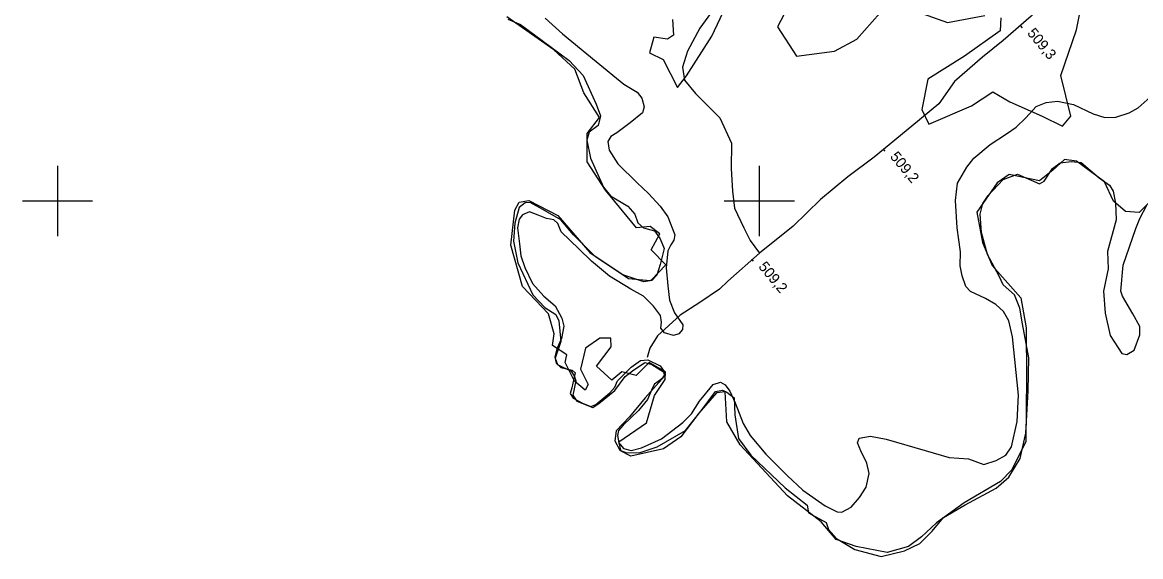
# Model space of a CAD drawing. Extents: x 347312 to 350503, y 6073086 to 6076432.
# Drawn here: x 348090 to 348408.7, y 6075298.7 to 6075450.8 of the extents above; entities that cross this region are included whole.
import ezdxf

# ---------------------------------------------------------------- set-up
doc = ezdxf.new("R2010")
doc.units = 0
for name, color, linetype in [('Level 2', 7, 'Continuous'), ('Level 22', 7, 'Continuous'), ('Level 3', 7, 'Continuous'), ('Level 4', 7, 'Continuous'), ('Level 44', 7, 'Continuous'), ('Level 61', 7, 'Continuous')]:
    doc.layers.add(name, color=color, linetype=linetype)

msp = doc.modelspace()

# ---------------------------------------------------------------- linework, layer by layer
at = {"layer": 'Level 2'}
for points in [[(348238.98, 6075452.05), (348243.95, 6075447.56), (348253.49, 6075439.72), (348261.38, 6075433.28), (348265.21, 6075430.93), (348266.57, 6075429.25), (348267.16, 6075426.82), (348266.74, 6075425.13), (348263.19, 6075422.28), (348259.41, 6075419.39), (348257.67, 6075418.32), (348256.83, 6075416.96), (348257.21, 6075414.47), (348259.71, 6075410.58), (348265.19, 6075405.18), (348268.47, 6075402.08), (348271.78, 6075398.47), (348273.92, 6075395.47), (348275.89, 6075390.32), (348275.69, 6075388.83), (348274.79, 6075387.54), (348273.93, 6075385.75), (348273.46, 6075380.96), (348273.98, 6075375.8), (348274.37, 6075371.74), (348275.81, 6075368.15), (348278.2, 6075364.69), (348278.1, 6075363.4), (348277.06, 6075362.13), (348275.58, 6075361.69), (348272.97, 6075362.43), (348271.99, 6075363.74), (348272.13, 6075365.45), (348271.85, 6075367.35), (348269.83, 6075370.06), (348266.96, 6075372.84), (348263.37, 6075374.89), (348257.32, 6075378.6), (348252.18, 6075382.81), (348248.56, 6075386.31), (348243.54, 6075391.16), (348242.58, 6075393.55), (348241.44, 6075394.59), (348239.38, 6075394.99), (348237, 6075395.92), (348234.47, 6075396.87), (348232.53, 6075396.04), (348231.56, 6075394.83), (348231.14, 6075392.35), (348231.71, 6075387.76), (348232.08, 6075384.34), (348233.18, 6075381), (348235.41, 6075376.47), (348238.58, 6075372.87), (348241.83, 6075370.13), (348243.77, 6075366.57), (348244.32, 6075364.36), (348243.59, 6075360.82), (348242.27, 6075357.84)], [(348363.99, 6075324.95), (348367.47, 6075326.08), (348370.25, 6075327.58), (348371.86, 6075329.98), (348373.48, 6075337.22), (348373.87, 6075344.64), (348372.11, 6075361.27), (348371.14, 6075365.83), (348369.55, 6075368.54), (348367.39, 6075370.5), (348364.47, 6075372.24), (348360.18, 6075374.19), (348358.85, 6075375.63), (348357.81, 6075378.66), (348357.27, 6075381.56), (348357.34, 6075385.5), (348356.36, 6075392.33), (348355.9, 6075400.13), (348356.5, 6075405.05), (348359.12, 6075409.63), (348361.12, 6075412.22), (348365.8, 6075416.09), (348370.48, 6075419.15), (348373.22, 6075421.01), (348375.96, 6075423.67), (348378.89, 6075426.9), (348381.71, 6075428.02), (348384.97, 6075428.44), (348389.5, 6075427.49), (348395.18, 6075424.83), (348398.46, 6075423.78), (348401.61, 6075423.84), (348405.39, 6075425.09), (348407.93, 6075426.53), (348411.43, 6075429.55)], [(348242.27, 6075357.84), (348241.72, 6075355.51), (348242.15, 6075353.75), (348243.43, 6075352.55), (348246.69, 6075351.82), (348247.49, 6075351.03), (348247.14, 6075349.4), (348246.57, 6075346.79), (348246.08, 6075345.18), (348246.97, 6075343.8), (348249.81, 6075342.32), (348251.98, 6075341.47), (348253.4, 6075342), (348257.43, 6075345.38), (348258.86, 6075346.98), (348259.59, 6075348.79), (348263.51, 6075352.62), (348266.12, 6075354.54), (348268.23, 6075354.71), (348271.77, 6075353.02), (348272.87, 6075351.41), (348273.01, 6075350.46), (348272.2, 6075349.38), (348270.12, 6075347.77), (348269.53, 6075346.74), (348268.1, 6075343.41), (348265.54, 6075340.33), (348261.23, 6075336.17), (348259.88, 6075334.64), (348259.62, 6075333.22), (348259.95, 6075331.1), (348261.27, 6075329.54), (348263.53, 6075328.91), (348266.41, 6075329.73), (348272.1, 6075332.24), (348278.25, 6075336.88), (348280.69, 6075339.33), (348282.93, 6075342.94), (348286.86, 6075347.71), (348288.93, 6075348.38), (348290.24, 6075347.62), (348291.61, 6075345.84), (348293.08, 6075342.54), (348295.41, 6075336.63), (348297.37, 6075333.22), (348301.85, 6075327.91), (348307.92, 6075321.82), (348312.41, 6075317.6), (348318.77, 6075313.21), (348322.23, 6075311.46), (348323.52, 6075311.34), (348326.16, 6075312.76), (348328.55, 6075315.58), (348330.45, 6075318.5), (348331.27, 6075322.39), (348330.64, 6075325.33), (348328.9, 6075328.8), (348328.01, 6075331.11), (348328.47, 6075332.44), (348331.69, 6075333.01), (348336.16, 6075332.11), (348347.3, 6075328.95), (348354.14, 6075326.98), (348359.6, 6075326.53), (348363.99, 6075324.95)]]:
    msp.add_lwpolyline(points, dxfattribs=at)
at = {"layer": 'Level 22'}
for points in [[(348386.72, 6075472.24), (348384.12, 6075463.82), (348381.61, 6075457.24), (348377.48, 6075452.61), (348369.52, 6075445.71), (348363.57, 6075440.92), (348355.61, 6075434.02), (348351.14, 6075427.61), (348343.48, 6075421.26), (348332.72, 6075412.48), (348325.21, 6075406.85), (348317.46, 6075400.43), (348309.68, 6075392.78), (348300.1, 6075385.13), (348291.06, 6075377.18), (348288.63, 6075374.86), (348283.01, 6075371.12), (348277.49, 6075367.44), (348271.04, 6075361.6), (348268.83, 6075358.1), (348268.08, 6075355.37)], [(348289.94, 6075458.64), (348283.06, 6075449.18), (348279.58, 6075442.69), (348278.16, 6075438.07), (348278.64, 6075434.41), (348281.81, 6075430.59), (348288.78, 6075423.62), (348292.05, 6075416.42), (348292.02, 6075409.19), (348292.4, 6075402.75), (348292.93, 6075397.94), (348295.61, 6075392.36), (348297.4, 6075388.75), (348300.1, 6075385.13)]]:
    msp.add_lwpolyline(points, dxfattribs=at)
at = {"layer": 'Level 3'}
for p, q in [((348374.38, 6075449.95), (348374.89, 6075449.33)), ((348335.29, 6075414.78), (348335.8, 6075414.16)), ((348297.79, 6075383.45), (348298.3, 6075382.83))]:
    msp.add_line(p, q, dxfattribs=at)
at = {"layer": 'Level 4'}
for points in [[(348228.32, 6075451.75), (348231.96, 6075450.27), (348238.14, 6075445.71), (348245.86, 6075440.03), (348249.84, 6075435.68), (348253.55, 6075427.57), (348254.72, 6075424.26), (348254.09, 6075421.48), (348251.52, 6075419.58), (348250.9, 6075417.34), (348251.94, 6075412.19), (348255.63, 6075403.92), (348257.58, 6075401.48), (348262.56, 6075398.55), (348264.52, 6075396.19), (348265.35, 6075393.73), (348266.98, 6075392.3), (348270.11, 6075391.44), (348271.79, 6075389.23), (348272.88, 6075386.46), (348271.76, 6075381.92), (348270.81, 6075378.88), (348269.36, 6075377.37), (348267.1, 6075377), (348261.07, 6075378.98), (348253.3, 6075384.12), (348247.04, 6075390.35), (348243.43, 6075394.59), (348238.34, 6075397.51), (348234.66, 6075399.56), (348233.25, 6075399.44), (348231.57, 6075398.11), (348230.38, 6075393.65), (348229.96, 6075388.55), (348231.2, 6075382.35), (348235.44, 6075373.29), (348238.89, 6075369.61), (348242.05, 6075367.64), (348242.87, 6075365.84), (348243.4, 6075359.95), (348241.86, 6075355.19), (348242.48, 6075353.45), (348246.42, 6075351.53), (348247.29, 6075350.22), (348247.69, 6075348.74), (348246.87, 6075344.66)], [(348368.31, 6075378.57), (348364.99, 6075384.76), (348363.32, 6075391.04), (348362.94, 6075396.22), (348363.72, 6075399.27), (348365.25, 6075401.59), (348369.54, 6075406.13), (348373.55, 6075407.65), (348379.83, 6075404.89), (348381.22, 6075405.67), (348383.57, 6075409.27), (348385.78, 6075410.88), (348388.9, 6075411.2), (348391.75, 6075410.94), (348396.86, 6075406.6), (348399.78, 6075404.44), (348400.86, 6075402.78), (348401.52, 6075399.35), (348401.66, 6075394.64), (348399.21, 6075385.62), (348399.4, 6075380.67), (348398.06, 6075374.29), (348398.54, 6075368), (348400, 6075361.69), (348403.35, 6075356.57), (348404.72, 6075356.28), (348406.85, 6075357.52), (348408.42, 6075361.9), (348408.48, 6075364.28), (348406.42, 6075367.84), (348403.52, 6075372.88), (348403, 6075374.33), (348403.65, 6075381.71), (348407.31, 6075392.19), (348408.47, 6075394.96), (348410.54, 6075399)], [(348246.87, 6075344.66), (348248.03, 6075342.99), (348252.52, 6075341.15), (348254.31, 6075342.35), (348258.8, 6075346.02), (348261.76, 6075350), (348263.88, 6075351.62), (348267.43, 6075353.97), (348269.4, 6075353.43), (348272.71, 6075351.36), (348272.96, 6075350.06), (348267.46, 6075343.89), (348263.02, 6075338.53), (348259.24, 6075334.55), (348258.82, 6075331.7), (348260.27, 6075329.06), (348262.25, 6075328.23), (348266.09, 6075328.34), (348270.88, 6075329.93), (348279, 6075334.59), (348283.75, 6075340.58), (348287.55, 6075345.72), (348289.48, 6075346.12), (348290.74, 6075345.51), (348292.87, 6075343.97), (348293.04, 6075339.05), (348294.07, 6075332.3), (348297.59, 6075327.62), (348307.33, 6075318.32), (348313.63, 6075313.39), (348314.01, 6075311.22), (348319.02, 6075308.38), (348319.71, 6075306.47), (348321.98, 6075303.84), (348327.26, 6075300.77), (348334.73, 6075298.71), (348341.38, 6075300.31), (348345.78, 6075302.45), (348349.24, 6075305.99), (348352.48, 6075309.89), (348358.7, 6075313.46), (348367.49, 6075318.2), (348371.08, 6075321.32), (348374.33, 6075326.65), (348375.92, 6075333.91), (348376.59, 6075345.89), (348376.78, 6075355.3), (348375.01, 6075364.96), (348374.24, 6075369.43), (348372.75, 6075373.23), (348369.52, 6075376.12), (348368.31, 6075378.57)]]:
    msp.add_lwpolyline(points, dxfattribs=at)
at = {"layer": 'Level 44'}
for points in [[(348275.27, 6075451.63), (348275.51, 6075447.18), (348273.85, 6075446.1), (348269.96, 6075446.62), (348268.72, 6075442.14), (348272.65, 6075440.3), (348276.73, 6075432.3), (348279.26, 6075435.59), (348286.52, 6075446.94), (348293.67, 6075462.27)], [(348308.97, 6075456.8), (348305.18, 6075449.61), (348310.62, 6075441.23), (348321.42, 6075442.69), (348327.81, 6075446.04), (348336.53, 6075455.98)], [(348339.24, 6075455.97), (348353.6, 6075450.79), (348364.29, 6075452.76)], [(348368.83, 6075452.17), (348368.64, 6075448.42), (348358.52, 6075441.23), (348348.05, 6075434.65), (348346.34, 6075426.02), (348348.32, 6075421.82), (348360.48, 6075427.1), (348366.52, 6075431.06), (348371.43, 6075428.22), (348380.57, 6075424.09), (348386.39, 6075421.25), (348388.8, 6075424.15), (348385.94, 6075435.75), (348390.37, 6075448.73), (348391.85, 6075455.82)], [(348282.81, 6075339.53), (348277.67, 6075332.83), (348272.67, 6075329.41), (348263.42, 6075327.28), (348260.68, 6075328.76), (348260.01, 6075331.37), (348267.83, 6075336.83), (348270.1, 6075344.6), (348273.14, 6075349.1), (348273.26, 6075351.31), (348268.58, 6075354.03), (348264.94, 6075350.24), (348260.84, 6075351.35), (348258, 6075348.97), (348253.59, 6075352.98), (348257.79, 6075358.44), (348257.68, 6075360.92), (348254.55, 6075360.87), (348250.43, 6075358.03), (348249.07, 6075352.07), (348251.22, 6075347.68), (348250.42, 6075346.11), (348247.36, 6075348.68), (348244.72, 6075354.02), (348245.16, 6075356.2), (348241.04, 6075358.79), (348241.59, 6075362.11), (348239.97, 6075367.85), (348232.54, 6075375.67), (348229.24, 6075387.4), (348230.31, 6075397.34), (348231.59, 6075399.61), (348234.35, 6075400.1), (348242.6, 6075395.83), (348251.68, 6075385.31), (348262.69, 6075377.91), (348268.89, 6075377.36), (348269.24, 6075377.5), (348273.34, 6075381.8), (348269.22, 6075386.04), (348271.62, 6075390.58), (348268.95, 6075392.72), (348265.05, 6075392.34), (348256.13, 6075403.1), (348250.98, 6075411.14), (348250.92, 6075419.19), (348254.47, 6075423.79), (348250.04, 6075430.77), (348247.47, 6075437.49), (348241.42, 6075442.98), (348228.04, 6075452.42)], [(348414.03, 6075402.63), (348408.29, 6075396.66), (348404.37, 6075397.03), (348400.94, 6075399.89), (348398.33, 6075405.39), (348390.42, 6075411.3), (348387.01, 6075411.78), (348383.68, 6075408.72), (348379.87, 6075405.71), (348371.16, 6075407.5), (348367.82, 6075405.18), (348362.01, 6075396.76), (348363.59, 6075388.15), (348366.34, 6075381.57), (348374.52, 6075372.43), (348376.02, 6075363.9), (348376.17, 6075349.75), (348375.94, 6075331.52), (348371.97, 6075323.42), (348368.7, 6075320.11), (348358.43, 6075314), (348350.5, 6075308.32), (348346.26, 6075304.36), (348342.55, 6075301.58), (348336.46, 6075299.85), (348327.65, 6075301.55), (348321.91, 6075303.55), (348317.68, 6075308.61), (348308.06, 6075315.97), (348294.57, 6075330.5), (348290.73, 6075337.09), (348290.27, 6075345.6), (348287.78, 6075345.33), (348282.81, 6075339.53)]]:
    msp.add_lwpolyline(points, dxfattribs=at)
at = {"layer": 'Level 61'}
for p, q in [((348100, 6075410), (348100, 6075390)), ((348300, 6075410), (348300, 6075390)), ((348090, 6075400), (348110, 6075400)), ((348290, 6075400), (348310, 6075400))]:
    msp.add_line(p, q, dxfattribs=at)

# ---------------------------------------------------------------- texts
at = {"layer": 'Level 3'}
for s, p in [('509,3', (348376.19, 6075447.71)), ('509,2', (348337.1, 6075412.54)), ('509,2', (348299.6, 6075381.21))]:
    msp.add_text(s, height=3, rotation=309.5679, dxfattribs=at).set_placement(p)

doc.saveas('drawing.dxf')
